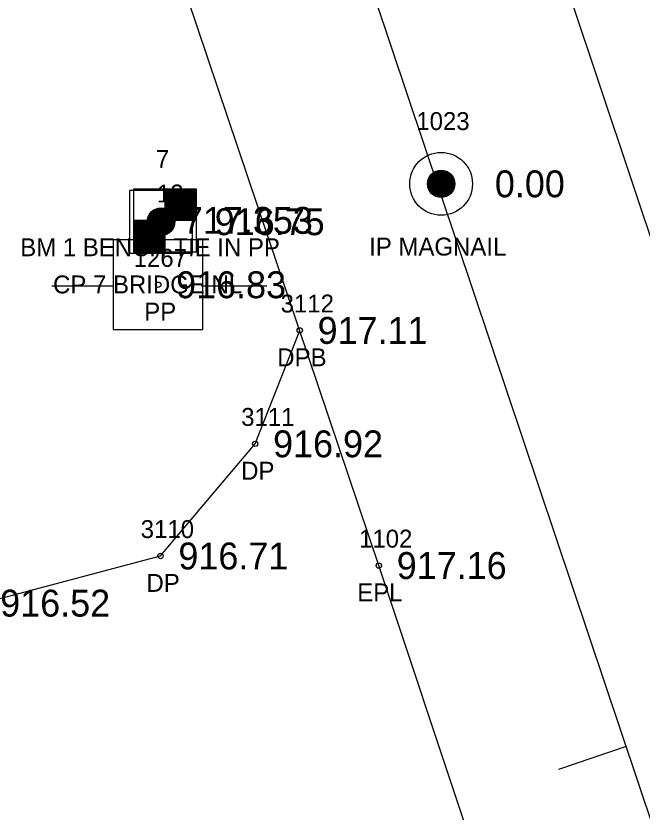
# Model space of a CAD drawing. Extents: x 1528109 to 1531398, y 1157799 to 1162548.
# Drawn here: x 1529800.4 to 1529835.35, y 1159719.34 to 1159763.76 of the extents above; entities that cross this region are included whole.
import ezdxf

# ---------------------------------------------------------------- set-up
doc = ezdxf.new("R2010")
doc.units = 0
for name, color, linetype in [('RD_EX_Driveway', 7, 'Continuous'), ('RD_EX_Driveway_txCode', 7, 'Continuous'), ('RD_EX_DV_Prop_txCode', 7, 'Continuous'), ('RD_EX_DV_PropPin', 7, 'Continuous'), ('RD_EX_Road', 7, 'Continuous'), ('RD_EX_Road_txCode', 7, 'Continuous'), ('RD_EX_TX_Driveway_ELEV', 7, 'Continuous'), ('RD_EX_TX_DV_Prop_ELEV', 7, 'Continuous'), ('RD_EX_TX_Road_ELEV', 7, 'Continuous'), ('RD_EX_UT', 7, 'Continuous'), ('RD_EX_UT_txCode', 7, 'Continuous'), ('RD_HC_Cl', 7, 'Continuous'), ('RD_HC_Data_Tic', 7, 'Continuous'), ('RD_HC_Survey', 7, 'Continuous'), ('RD_HC_Survey_ELEV', 7, 'Continuous'), ('RD_HC_Survey_txCode', 7, 'Continuous'), ('RD_SMD_Locator', 7, 'Continuous')]:
    doc.layers.add(name, color=color, linetype=linetype)

msp = doc.modelspace()

# ---------------------------------------------------------------- linework, layer by layer
at = {"layer": 'RD_EX_Driveway'}
msp.add_lwpolyline([(1529787.584, 1159831.154), (1529780.256, 1159834.104), (1529766.864, 1159832.732), (1529758.061, 1159824.497), (1529754.832, 1159814.109), (1529754.689, 1159790.856), (1529758.886, 1159772.324), (1529770.422, 1159750.594), (1529785.672, 1159734.658), (1529798.526, 1159730.996), (1529808.471, 1159733.627), (1529813.755, 1159739.883), (1529816.241, 1159746.211)], dxfattribs=at)
at = {"layer": 'RD_EX_DV_PropPin'}
for p, q in [((1529823.679, 1159753.778), (1529823.679, 1159754.997)), ((1529823.714, 1159753.753), (1529823.714, 1159755.022)), ((1529823.749, 1159753.731), (1529823.749, 1159755.044)), ((1529823.784, 1159753.712), (1529823.784, 1159755.063)), ((1529823.819, 1159753.695), (1529823.819, 1159755.08)), ((1529823.854, 1159753.68), (1529823.854, 1159755.095)), ((1529823.889, 1159753.667), (1529823.889, 1159755.108)), ((1529823.924, 1159753.656), (1529823.924, 1159755.119)), ((1529823.959, 1159753.647), (1529823.959, 1159755.128)), ((1529823.994, 1159753.64), (1529823.994, 1159755.136)), ((1529824.029, 1159753.634), (1529824.029, 1159755.141)), ((1529824.064, 1159753.63), (1529824.064, 1159755.145)), ((1529824.099, 1159753.627), (1529824.099, 1159755.148)), ((1529824.134, 1159753.627), (1529824.134, 1159755.149)), ((1529824.169, 1159753.627), (1529824.169, 1159755.148)), ((1529824.204, 1159753.63), (1529824.204, 1159755.145)), ((1529824.239, 1159753.634), (1529824.239, 1159755.141)), ((1529824.274, 1159753.64), (1529824.274, 1159755.136)), ((1529824.309, 1159753.647), (1529824.309, 1159755.128)), ((1529824.344, 1159753.656), (1529824.344, 1159755.119)), ((1529824.379, 1159753.667), (1529824.379, 1159755.108)), ((1529824.414, 1159753.68), (1529824.414, 1159755.095)), ((1529824.45, 1159753.695), (1529824.45, 1159755.08)), ((1529824.485, 1159753.712), (1529824.485, 1159755.063)), ((1529824.52, 1159753.731), (1529824.52, 1159755.044)), ((1529824.555, 1159753.753), (1529824.555, 1159755.022)), ((1529824.59, 1159753.778), (1529824.59, 1159754.997)), ((1529823.399, 1159754.191), (1529823.399, 1159754.584)), ((1529823.434, 1159754.09), (1529823.434, 1159754.686)), ((1529823.469, 1159754.018), (1529823.469, 1159754.757)), ((1529823.504, 1159753.961), (1529823.504, 1159754.814)), ((1529823.539, 1159753.913), (1529823.539, 1159754.862)), ((1529823.574, 1159753.873), (1529823.574, 1159754.903)), ((1529823.609, 1159753.837), (1529823.609, 1159754.938)), ((1529823.644, 1159753.805), (1529823.644, 1159754.97)), ((1529824.625, 1159753.805), (1529824.625, 1159754.97)), ((1529824.66, 1159753.837), (1529824.66, 1159754.938)), ((1529824.695, 1159753.873), (1529824.695, 1159754.903)), ((1529824.73, 1159753.913), (1529824.73, 1159754.862)), ((1529824.765, 1159753.961), (1529824.765, 1159754.814)), ((1529824.8, 1159754.018), (1529824.8, 1159754.757)), ((1529824.835, 1159754.09), (1529824.835, 1159754.686)), ((1529824.87, 1159754.191), (1529824.87, 1159754.584))]:
    msp.add_line(p, q, dxfattribs=at)
for radius in [1.75, 0.761]:
    msp.add_circle((1529824.134, 1159754.388), radius, dxfattribs=at)
at = {"layer": 'RD_EX_Road'}
for points in [[(1530337.524, 1159156.438), (1530294.126, 1159166.929), (1530250.926, 1159177.698), (1530204.422, 1159191.501), (1530168.451, 1159204.972), (1530120.583, 1159231.544), (1530104.564, 1159243.153), (1530086.767, 1159257.614), (1530051.976, 1159290.884), (1530019.197, 1159326.185), (1529978.154, 1159378.313), (1529959.682, 1159408.202), (1529942.811, 1159442.343), (1529934.787, 1159460.877), (1529923.222, 1159491.089), (1529910.457, 1159527.951), (1529895.986, 1159570.934), (1529881.686, 1159613.98), (1529856.284, 1159690.671), (1529839.736, 1159739.707), (1529819.567, 1159800.037), (1529788.948, 1159890.988)], [(1530332.276, 1159136.668), (1530288.961, 1159147.056), (1530245.679, 1159158.002), (1530197.525, 1159172.184), (1530159.104, 1159186.574), (1530108.597, 1159214.893), (1530072.674, 1159242.37), (1530037.118, 1159276.962), (1530005.208, 1159311.503), (1529961.591, 1159366.877), (1529941.786, 1159398.289), (1529924.064, 1159434.111), (1529903.768, 1159484.387), (1529891.443, 1159520.805), (1529876.794, 1159564.704), (1529862.9, 1159606.82), (1529836.939, 1159684.287), (1529820.656, 1159733.094), (1529800.023, 1159794.401), (1529769.543, 1159884.464)]]:
    msp.add_lwpolyline(points, dxfattribs=at)
at = {"layer": 'RD_EX_UT'}
for p, q in [((1529810.836, 1159751.267), (1529805.836, 1159751.267)), ((1529805.836, 1159751.267), (1529805.836, 1159746.267)), ((1529810.836, 1159746.267), (1529810.836, 1159751.267)), ((1529802.404, 1159748.705), (1529805.874, 1159748.705)), ((1529810.764, 1159748.705), (1529814.404, 1159748.705)), ((1529805.836, 1159746.267), (1529810.836, 1159746.267))]:
    msp.add_line(p, q, dxfattribs=at)
at = {"layer": 'RD_HC_Cl'}
msp.add_line((1529913.495, 1159487.738), (1529527.854, 1160635.768), dxfattribs=at)
at = {"layer": 'RD_HC_Data_Tic'}
msp.add_line((1529834.468, 1159722.997), (1529830.676, 1159721.723), dxfattribs=at)
at = {"layer": 'RD_HC_Survey'}
for p, q in [((1529808.723, 1159754.1), (1529808.723, 1159750.6)), ((1529808.74, 1159754.1), (1529808.74, 1159752.35)), ((1529808.765, 1159754.1), (1529808.765, 1159752.35)), ((1529808.79, 1159754.1), (1529808.79, 1159752.35)), ((1529808.815, 1159754.1), (1529808.815, 1159752.35)), ((1529808.839, 1159754.1), (1529808.839, 1159752.35)), ((1529808.864, 1159754.1), (1529808.864, 1159752.35)), ((1529808.889, 1159754.1), (1529808.889, 1159752.35)), ((1529808.914, 1159754.1), (1529808.914, 1159752.35)), ((1529808.938, 1159754.1), (1529808.938, 1159752.35)), ((1529808.963, 1159754.1), (1529808.963, 1159752.35)), ((1529808.988, 1159754.1), (1529808.988, 1159752.35)), ((1529809.013, 1159754.1), (1529809.013, 1159752.35)), ((1529809.037, 1159754.1), (1529809.037, 1159752.35)), ((1529809.062, 1159754.1), (1529809.062, 1159752.35)), ((1529809.087, 1159754.1), (1529809.087, 1159752.35)), ((1529809.112, 1159754.1), (1529809.112, 1159752.35)), ((1529809.136, 1159754.1), (1529809.136, 1159752.35)), ((1529809.161, 1159754.1), (1529809.161, 1159752.35)), ((1529809.186, 1159754.1), (1529809.186, 1159752.35)), ((1529809.211, 1159754.1), (1529809.211, 1159752.35)), ((1529809.235, 1159754.1), (1529809.235, 1159752.35)), ((1529809.26, 1159754.1), (1529809.26, 1159752.35)), ((1529809.285, 1159754.1), (1529809.285, 1159752.35)), ((1529809.31, 1159754.1), (1529809.31, 1159752.35)), ((1529809.334, 1159754.1), (1529809.334, 1159752.35)), ((1529809.359, 1159754.1), (1529809.359, 1159752.35)), ((1529809.384, 1159754.1), (1529809.384, 1159752.35)), ((1529809.409, 1159754.1), (1529809.409, 1159752.35)), ((1529809.433, 1159754.1), (1529809.433, 1159752.35)), ((1529809.458, 1159754.1), (1529809.458, 1159752.35)), ((1529809.483, 1159754.1), (1529809.483, 1159752.35)), ((1529809.507, 1159754.1), (1529809.507, 1159752.35)), ((1529809.532, 1159754.1), (1529809.532, 1159752.35)), ((1529809.557, 1159754.1), (1529809.557, 1159752.35)), ((1529809.582, 1159754.1), (1529809.582, 1159752.35)), ((1529809.606, 1159754.1), (1529809.606, 1159752.35)), ((1529809.631, 1159754.1), (1529809.631, 1159752.35)), ((1529809.656, 1159754.1), (1529809.656, 1159752.35)), ((1529809.681, 1159754.1), (1529809.681, 1159752.35)), ((1529809.705, 1159754.1), (1529809.705, 1159752.35)), ((1529809.73, 1159754.1), (1529809.73, 1159752.35)), ((1529809.755, 1159754.1), (1529809.755, 1159752.35)), ((1529809.78, 1159754.1), (1529809.78, 1159752.35)), ((1529809.804, 1159754.1), (1529809.804, 1159752.35)), ((1529809.829, 1159754.1), (1529809.829, 1159752.35)), ((1529809.854, 1159754.1), (1529809.854, 1159752.35)), ((1529809.879, 1159754.1), (1529809.879, 1159752.35)), ((1529809.903, 1159754.1), (1529809.903, 1159752.35)), ((1529809.928, 1159754.1), (1529809.928, 1159752.35)), ((1529809.953, 1159754.1), (1529809.953, 1159752.35)), ((1529809.978, 1159754.1), (1529809.978, 1159752.35)), ((1529810.002, 1159754.1), (1529810.002, 1159752.35)), ((1529810.027, 1159754.1), (1529810.027, 1159752.35)), ((1529810.052, 1159754.1), (1529810.052, 1159752.35)), ((1529810.077, 1159754.1), (1529810.077, 1159752.35)), ((1529810.101, 1159754.1), (1529810.101, 1159752.35)), ((1529810.126, 1159754.1), (1529810.126, 1159752.35)), ((1529810.151, 1159754.1), (1529810.151, 1159752.35)), ((1529810.176, 1159754.1), (1529810.176, 1159752.35)), ((1529810.2, 1159754.1), (1529810.2, 1159752.35)), ((1529810.225, 1159754.1), (1529810.225, 1159752.35)), ((1529810.25, 1159754.1), (1529810.25, 1159752.35)), ((1529810.275, 1159754.1), (1529810.275, 1159752.35)), ((1529810.299, 1159754.1), (1529810.299, 1159752.35)), ((1529810.324, 1159754.1), (1529810.324, 1159752.35)), ((1529810.349, 1159754.1), (1529810.349, 1159752.35)), ((1529810.374, 1159754.1), (1529810.374, 1159752.35)), ((1529810.398, 1159754.1), (1529810.398, 1159752.35)), ((1529810.423, 1159754.1), (1529810.423, 1159752.35)), ((1529810.448, 1159754.1), (1529810.448, 1159752.35)), ((1529807.9, 1159751.793), (1529807.9, 1159752.757)), ((1529807.925, 1159751.764), (1529807.925, 1159752.786)), ((1529807.95, 1159751.737), (1529807.95, 1159752.813)), ((1529807.974, 1159751.713), (1529807.974, 1159752.837)), ((1529807.999, 1159751.691), (1529807.999, 1159752.859)), ((1529808.024, 1159751.67), (1529808.024, 1159752.879)), ((1529808.049, 1159751.652), (1529808.049, 1159752.898)), ((1529808.073, 1159751.635), (1529808.073, 1159752.915)), ((1529808.098, 1159751.619), (1529808.098, 1159752.931)), ((1529808.123, 1159751.604), (1529808.123, 1159752.946)), ((1529808.148, 1159751.591), (1529808.148, 1159752.959)), ((1529808.172, 1159751.579), (1529808.172, 1159752.971)), ((1529808.197, 1159751.568), (1529808.197, 1159752.982)), ((1529808.222, 1159751.557), (1529808.222, 1159752.992)), ((1529808.247, 1159751.548), (1529808.247, 1159753.001)), ((1529808.271, 1159751.54), (1529808.271, 1159753.01)), ((1529808.296, 1159751.533), (1529808.296, 1159753.017)), ((1529808.321, 1159751.527), (1529808.321, 1159753.023)), ((1529808.346, 1159751.521), (1529808.346, 1159753.029)), ((1529808.37, 1159751.516), (1529808.37, 1159753.033)), ((1529808.395, 1159751.513), (1529808.395, 1159753.037)), ((1529808.42, 1159751.51), (1529808.42, 1159753.04)), ((1529808.445, 1159751.507), (1529808.445, 1159753.042)), ((1529808.469, 1159751.506), (1529808.469, 1159753.044)), ((1529808.494, 1159751.505), (1529808.494, 1159753.044)), ((1529808.519, 1159751.506), (1529808.519, 1159753.044)), ((1529808.544, 1159751.507), (1529808.544, 1159753.043)), ((1529808.568, 1159751.508), (1529808.568, 1159753.041)), ((1529808.593, 1159751.511), (1529808.593, 1159753.039)), ((1529808.618, 1159751.514), (1529808.618, 1159753.035)), ((1529808.643, 1159751.519), (1529808.643, 1159753.031)), ((1529808.667, 1159751.524), (1529808.667, 1159753.026)), ((1529808.692, 1159751.53), (1529808.692, 1159753.02)), ((1529808.717, 1159751.537), (1529808.717, 1159753.013)), ((1529808.741, 1159751.544), (1529808.741, 1159753.005)), ((1529808.766, 1159751.553), (1529808.766, 1159752.997)), ((1529808.791, 1159751.563), (1529808.791, 1159752.987)), ((1529808.816, 1159751.573), (1529808.816, 1159752.977)), ((1529808.84, 1159751.585), (1529808.84, 1159752.965)), ((1529808.865, 1159751.598), (1529808.865, 1159752.952)), ((1529808.89, 1159751.612), (1529808.89, 1159752.938)), ((1529808.915, 1159751.627), (1529808.915, 1159752.923)), ((1529808.939, 1159751.643), (1529808.939, 1159752.906)), ((1529808.964, 1159751.661), (1529808.964, 1159752.888)), ((1529808.989, 1159751.681), (1529808.989, 1159752.869)), ((1529809.014, 1159751.702), (1529809.014, 1159752.848)), ((1529809.038, 1159751.725), (1529809.038, 1159752.824)), ((1529809.063, 1159751.751), (1529809.063, 1159752.799)), ((1529809.088, 1159751.779), (1529809.088, 1159752.771)), ((1529810.473, 1159752.35), (1529806.973, 1159752.35)), ((1529806.973, 1159752.35), (1529806.973, 1159750.6)), ((1529806.997, 1159752.35), (1529806.997, 1159750.6)), ((1529807.022, 1159752.35), (1529807.022, 1159750.6)), ((1529807.047, 1159752.35), (1529807.047, 1159750.6)), ((1529807.072, 1159752.35), (1529807.072, 1159750.6)), ((1529807.096, 1159752.35), (1529807.096, 1159750.6)), ((1529807.121, 1159752.35), (1529807.121, 1159750.6)), ((1529807.146, 1159752.35), (1529807.146, 1159750.6)), ((1529807.171, 1159752.35), (1529807.171, 1159750.6)), ((1529807.195, 1159752.35), (1529807.195, 1159750.6)), ((1529807.22, 1159752.35), (1529807.22, 1159750.6)), ((1529807.245, 1159752.35), (1529807.245, 1159750.6)), ((1529807.27, 1159752.35), (1529807.27, 1159750.6)), ((1529807.294, 1159752.35), (1529807.294, 1159750.6)), ((1529807.319, 1159752.35), (1529807.319, 1159750.6)), ((1529807.344, 1159752.35), (1529807.344, 1159750.6)), ((1529807.369, 1159752.35), (1529807.369, 1159750.6)), ((1529807.393, 1159752.35), (1529807.393, 1159750.6)), ((1529807.418, 1159752.35), (1529807.418, 1159750.6)), ((1529807.443, 1159752.35), (1529807.443, 1159750.6)), ((1529807.468, 1159752.35), (1529807.468, 1159750.6)), ((1529807.492, 1159752.35), (1529807.492, 1159750.6)), ((1529807.517, 1159752.35), (1529807.517, 1159750.6)), ((1529807.542, 1159752.35), (1529807.542, 1159750.6)), ((1529807.567, 1159752.35), (1529807.567, 1159750.6)), ((1529807.591, 1159752.35), (1529807.591, 1159750.6)), ((1529807.616, 1159752.35), (1529807.616, 1159750.6)), ((1529807.641, 1159752.35), (1529807.641, 1159750.6)), ((1529807.666, 1159752.35), (1529807.666, 1159750.6)), ((1529807.69, 1159752.35), (1529807.69, 1159750.6)), ((1529807.715, 1159752.35), (1529807.715, 1159750.6)), ((1529807.74, 1159752.35), (1529807.74, 1159750.6)), ((1529807.752, 1159752.096), (1529807.752, 1159752.454)), ((1529807.765, 1159752.35), (1529807.765, 1159750.6)), ((1529807.776, 1159752.013), (1529807.776, 1159752.537)), ((1529807.789, 1159752.35), (1529807.789, 1159750.6)), ((1529807.801, 1159751.953), (1529807.801, 1159752.597)), ((1529807.814, 1159752.35), (1529807.814, 1159750.6)), ((1529807.826, 1159751.904), (1529807.826, 1159752.646)), ((1529807.839, 1159752.35), (1529807.839, 1159750.6)), ((1529807.851, 1159751.862), (1529807.851, 1159752.688)), ((1529807.864, 1159752.35), (1529807.864, 1159750.6)), ((1529807.875, 1159751.825), (1529807.875, 1159752.724)), ((1529807.888, 1159752.35), (1529807.888, 1159750.6)), ((1529807.913, 1159752.35), (1529807.913, 1159750.6)), ((1529807.938, 1159752.35), (1529807.938, 1159750.6)), ((1529807.963, 1159752.35), (1529807.963, 1159750.6)), ((1529807.987, 1159752.35), (1529807.987, 1159750.6)), ((1529808.012, 1159752.35), (1529808.012, 1159750.6)), ((1529808.037, 1159752.35), (1529808.037, 1159750.6)), ((1529808.062, 1159752.35), (1529808.062, 1159750.6)), ((1529808.086, 1159752.35), (1529808.086, 1159750.6)), ((1529808.111, 1159752.35), (1529808.111, 1159750.6)), ((1529808.136, 1159752.35), (1529808.136, 1159750.6)), ((1529808.161, 1159752.35), (1529808.161, 1159750.6)), ((1529808.185, 1159752.35), (1529808.185, 1159750.6)), ((1529808.21, 1159752.35), (1529808.21, 1159750.6)), ((1529808.235, 1159752.35), (1529808.235, 1159750.6)), ((1529808.26, 1159752.35), (1529808.26, 1159750.6)), ((1529808.284, 1159752.35), (1529808.284, 1159750.6)), ((1529808.309, 1159752.35), (1529808.309, 1159750.6)), ((1529808.334, 1159752.35), (1529808.334, 1159750.6)), ((1529808.359, 1159752.35), (1529808.359, 1159750.6)), ((1529808.383, 1159752.35), (1529808.383, 1159750.6)), ((1529808.408, 1159752.35), (1529808.408, 1159750.6)), ((1529808.433, 1159752.35), (1529808.433, 1159750.6)), ((1529808.458, 1159752.35), (1529808.458, 1159750.6)), ((1529808.482, 1159752.35), (1529808.482, 1159750.6)), ((1529808.507, 1159752.35), (1529808.507, 1159750.6)), ((1529808.532, 1159752.35), (1529808.532, 1159750.6)), ((1529808.557, 1159752.35), (1529808.557, 1159750.6)), ((1529808.581, 1159752.35), (1529808.581, 1159750.6)), ((1529808.606, 1159752.35), (1529808.606, 1159750.6)), ((1529808.631, 1159752.35), (1529808.631, 1159750.6)), ((1529808.656, 1159752.35), (1529808.656, 1159750.6)), ((1529808.68, 1159752.35), (1529808.68, 1159750.6)), ((1529808.705, 1159752.35), (1529808.705, 1159750.6)), ((1529809.113, 1159751.81), (1529809.113, 1159752.74)), ((1529809.137, 1159751.844), (1529809.137, 1159752.706)), ((1529809.162, 1159751.883), (1529809.162, 1159752.667)), ((1529809.187, 1159751.928), (1529809.187, 1159752.621)), ((1529809.212, 1159751.983), (1529809.212, 1159752.567)), ((1529809.236, 1159752.052), (1529809.236, 1159752.498)), ((1529809.261, 1159752.163), (1529809.261, 1159752.387))]:
    msp.add_line(p, q, dxfattribs=at)
for points in [[(1529810.473, 1159754.1), (1529806.973, 1159754.1), (1529806.973, 1159750.6), (1529810.473, 1159750.6)], [(1529810.25, 1159754.025), (1529806.75, 1159754.025), (1529806.75, 1159750.525), (1529810.25, 1159750.525)]]:
    msp.add_lwpolyline(points, close=True, dxfattribs=at)
msp.add_circle((1529808.5, 1159752.275), 0.769, dxfattribs=at)
at = {"layer": 'RD_SMD_Locator'}
for centre in [(1529824.134, 1159754.388), (1529808.5, 1159752.275), (1529808.723, 1159752.35), (1529808.345, 1159748.758), (1529816.241, 1159746.211), (1529813.755, 1159739.883), (1529808.471, 1159733.627), (1529820.656, 1159733.094)]:
    msp.add_circle(centre, 0.15, dxfattribs=at)

# ---------------------------------------------------------------- texts
at = {"layer": 'RD_EX_Driveway_txCode'}
for s, p in [('3112', (1529815.178, 1159747.211)), ('DPB', (1529814.989, 1159744.211)), ('3111', (1529812.975, 1159740.883)), ('DP', (1529812.975, 1159737.883)), ('3110', (1529807.368, 1159734.627)), ('DP', (1529807.691, 1159731.627))]:
    msp.add_text(s, height=1, dxfattribs=at).set_placement(p)
at = {"layer": 'RD_EX_DV_Prop_txCode'}
for s, p in [('1023', (1529822.749, 1159757.388)), ('IP MAGNAIL', (1529820.119, 1159750.388))]:
    msp.add_text(s, height=1, dxfattribs=at).set_placement(p)
at = {"layer": 'RD_EX_Road_txCode'}
for s, p in [('1102', (1529819.553, 1159734.094)), ('EPL', (1529819.451, 1159731.094))]:
    msp.add_text(s, height=1, dxfattribs=at).set_placement(p)
at = {"layer": 'RD_EX_TX_Driveway_ELEV'}
for s, p in [('917.11', (1529817.241, 1159745.461)), ('916.92', (1529814.755, 1159739.133)), ('916.71', (1529809.471, 1159732.877)), ('916.52', (1529799.526, 1159730.246))]:
    msp.add_text(s, height=1.5, dxfattribs=at).set_placement(p)
at = {"layer": 'RD_EX_TX_DV_Prop_ELEV'}
msp.add_text('0.00', height=1.5, dxfattribs=at).set_placement((1529827.134, 1159753.638))
at = {"layer": 'RD_EX_TX_Road_ELEV'}
msp.add_text('917.16', height=1.5, dxfattribs=at).set_placement((1529821.656, 1159732.344))
at = {"layer": 'RD_EX_UT_txCode'}
for s, p in [('1267', (1529806.975, 1159749.758)), ('PP', (1529807.565, 1159746.758))]:
    msp.add_text(s, height=1, dxfattribs=at).set_placement(p)
at = {"layer": 'RD_HC_Survey_ELEV'}
for s, p in [('717.353', (1529809.723, 1159751.6)), ('916.75', (1529811.5, 1159751.525)), ('916.83', (1529809.345, 1159748.008))]:
    msp.add_text(s, height=1.5, dxfattribs=at).set_placement(p)
at = {"layer": 'RD_HC_Survey_txCode'}
for s, p in [('7', (1529808.216, 1159755.275)), ('12', (1529808.274, 1159753.35)), ('BM 1 BENCH TIE IN PP', (1529800.644, 1159750.35)), ('CP 7 BRIDGE NL', (1529802.476, 1159748.275))]:
    msp.add_text(s, height=1, dxfattribs=at).set_placement(p)

doc.saveas('drawing.dxf')
